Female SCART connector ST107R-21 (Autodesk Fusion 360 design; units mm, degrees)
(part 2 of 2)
sketch "Sketch19" plane through (0, 10, 0) normal (0, 1, 0) x axis (-1, 0, 0)
  line L1 (-41.65, 0) -> (-41.65, 5.21)
  line L2 (-39.24, 0) -> (-41.65, 0)
  line L3 (-39.24, 5.21) -> (-39.24, 0)
  line L4 (-39.74, 5.21) -> (-39.24, 5.21)
  line L5 (-39.74, 6.21) -> (-39.74, 5.21)
  line L6 (-37.34, 6.21) -> (-39.74, 6.21)
  line L7 (-37.34, 5.21) -> (-37.34, 6.21)
  line L8 (-37.84, 5.21) -> (-37.34, 5.21)
  line L9 (-37.84, 0) -> (-37.84, 5.21)
  line L10 (-35.43, 0) -> (-37.84, 0)
  line L11 (-35.43, 5.21) -> (-35.43, 0)
  line L12 (-35.93, 5.21) -> (-35.43, 5.21)
  line L13 (-35.93, 6.21) -> (-35.93, 5.21)
  line L14 (-33.53, 6.21) -> (-35.93, 6.21)
  line L15 (-33.53, 5.21) -> (-33.53, 6.21)
  line L16 (-34.03, 5.21) -> (-33.53, 5.21)
  line L17 (-34.03, 0) -> (-34.03, 5.21)
  line L18 (-31.62, 0) -> (-34.03, 0)
  line L19 (-31.62, 5.21) -> (-31.62, 0)
  line L20 (-32.12, 5.21) -> (-31.62, 5.21)
  line L21 (-32.12, 6.21) -> (-32.12, 5.21)
  line L22 (-29.72, 6.21) -> (-32.12, 6.21)
  line L23 (-29.72, 5.21) -> (-29.72, 6.21)
  line L24 (-30.22, 5.21) -> (-29.72, 5.21)
  line L25 (-30.22, 0) -> (-30.22, 5.21)
  line L26 (-27.81, 0) -> (-30.22, 0)
  line L27 (-27.81, 5.21) -> (-27.81, 0)
  line L28 (-28.31, 5.21) -> (-27.81, 5.21)
  line L29 (-28.31, 6.21) -> (-28.31, 5.21)
  line L30 (-25.91, 6.21) -> (-28.31, 6.21)
  line L31 (-25.91, 5.21) -> (-25.91, 6.21)
  line L32 (-26.41, 5.21) -> (-25.91, 5.21)
  line L33 (-26.41, 0) -> (-26.41, 5.21)
  line L34 (-24, 0) -> (-26.41, 0)
  line L35 (-24, 5.21) -> (-24, 0)
  line L36 (-24.5, 5.21) -> (-24, 5.21)
  line L37 (-24.5, 6.21) -> (-24.5, 5.21)
  line L38 (-22.1, 6.21) -> (-24.5, 6.21)
  line L39 (-22.1, 5.21) -> (-22.1, 6.21)
  line L40 (-22.6, 5.21) -> (-22.1, 5.21)
  line L41 (-22.6, 0) -> (-22.6, 5.21)
  line L42 (-20.19, 0) -> (-22.6, 0)
  line L43 (-20.19, 5.21) -> (-20.19, 0)
  line L44 (-20.69, 5.21) -> (-20.19, 5.21)
  line L45 (-20.69, 6.21) -> (-20.69, 5.21)
  line L46 (-18.29, 6.21) -> (-20.69, 6.21)
  line L47 (-18.29, 5.21) -> (-18.29, 6.21)
  line L48 (-18.79, 5.21) -> (-18.29, 5.21)
  line L49 (-18.79, 0) -> (-18.79, 5.21)
  line L50 (-16.38, 0) -> (-18.79, 0)
  line L51 (-16.38, 5.21) -> (-16.38, 0)
  line L52 (-16.88, 5.21) -> (-16.38, 5.21)
  line L53 (-16.88, 6.21) -> (-16.88, 5.21)
  line L54 (-14.48, 6.21) -> (-16.88, 6.21)
  line L55 (-14.48, 5.21) -> (-14.48, 6.21)
  line L56 (-14.98, 5.21) -> (-14.48, 5.21)
  line L57 (-14.98, 0) -> (-14.98, 5.21)
  line L58 (-12.57, 0) -> (-14.98, 0)
  line L59 (-12.57, 5.21) -> (-12.57, 0)
  line L60 (-13.07, 5.21) -> (-12.57, 5.21)
  line L61 (-13.07, 6.21) -> (-13.07, 5.21)
  line L62 (-10.67, 6.21) -> (-13.07, 6.21)
  line L63 (-10.67, 5.21) -> (-10.67, 6.21)
  line L64 (-11.17, 5.21) -> (-10.67, 5.21)
  line L65 (-11.17, 0) -> (-11.17, 5.21)
  line L66 (-8.76, 0) -> (-11.17, 0)
  line L67 (-8.76, 5.21) -> (-8.76, 0)
  line L68 (-9.26, 5.21) -> (-8.76, 5.21)
  line L69 (-9.26, 6.21) -> (-9.26, 5.21)
  line L70 (-6.86, 6.21) -> (-9.26, 6.21)
  line L71 (-6.86, 5.21) -> (-6.86, 6.21)
  line L72 (-7.36, 5.21) -> (-6.86, 5.21)
  line L73 (-7.36, 0) -> (-7.36, 5.21)
  line L74 (-5.0797, 0) -> (-7.36, 0)
  line L75 (-4.95, 5.21) -> (-4.95, 0.0028)
  line L76 (-5.45, 5.21) -> (-4.95, 5.21)
  line L77 (-5.45, 6.21) -> (-5.45, 5.21)
  line L78 (-3.05, 6.21) -> (-5.45, 6.21)
  line L79 (-3.05, 5.21) -> (-3.05, 6.21)
  line L80 (-3.55, 5.21) -> (-3.05, 5.21)
  line L81 (-3.55, 0.4193) -> (-3.55, 5.21)
  line L82 (-1.8712, 4.15) -> (-2.1135, 2.5506)
  line L83 (1.2056, 4.15) -> (-1.8712, 4.15)
  line L84 (1.2056, -1.7) -> (1.2056, 4.15)
  line L85 (0.2056, -1.7) -> (1.2056, -1.7)
  line L86 (2.7056, -6) -> (0.2056, -1.7)
  line L87 (2.7056, 4.15) -> (2.7056, -6)
  line L88 (3.2056, 4.15) -> (2.7056, 4.15)
  line L89 (3.2056, 12.35) -> (3.2056, 4.15)
  line L90 (-0.6288, 12.35) -> (3.2056, 12.35)
  line L91 (-0.5226, 13.0506) -> (-0.6288, 12.35)
  line L92 (-44.1, 16.5) -> (-3.4888, 16.5)
  line L93 (-47.1, 12.35) -> (-47.1, 13.5)
  line L94 (-50.7944, 12.35) -> (-47.1, 12.35)
  line L95 (-50.7944, 4.15) -> (-50.7944, 12.35)
  line L96 (-50.2944, 4.15) -> (-50.7944, 4.15)
  line L97 (-50.2944, -6) -> (-50.2944, 4.15)
  line L98 (-47.7944, -1.7) -> (-50.2944, -6)
  line L99 (-48.7944, -1.7) -> (-47.7944, -1.7)
  line L100 (-48.7944, 4.15) -> (-48.7944, -1.7)
  line L101 (-47.1, 4.15) -> (-48.7944, 4.15)
  line L102 (-47.1, 3) -> (-47.1, 4.15)
  line L103 (-43.05, 0) -> (-44.1, 0)
  line L104 (-43.05, 5.21) -> (-43.05, 0)
  line L105 (-43.55, 5.21) -> (-43.05, 5.21)
  line L106 (-43.55, 6.21) -> (-43.55, 5.21)
  line L107 (-41.15, 6.21) -> (-43.55, 6.21)
  line L108 (-41.15, 5.21) -> (-41.15, 6.21)
  line L109 (-41.65, 5.21) -> (-41.15, 5.21)
  line L110 (2.2056, 10.35) -> (-0.4884, 10.35)
  line L111 (2.2056, 6.15) -> (2.2056, 10.35)
  line L112 (-0.4884, 6.15) -> (2.2056, 6.15)
  line L113 (-0.4884, 10.35) -> (-0.4884, 6.15)
  line L114 (-49.7944, 6.15) -> (-47.1, 6.15)
  line L115 (-49.7944, 10.35) -> (-49.7944, 6.15)
  line L116 (-47.1, 10.35) -> (-49.7944, 10.35)
  line L117 (-47.1, 6.15) -> (-47.1, 10.35)
  line L118 (-26.405, 11.29) -> (-26.405, 10.29)
  line L119 (-24.005, 11.29) -> (-26.405, 11.29)
  line L120 (-24.005, 10.29) -> (-24.005, 11.29)
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  dimension "d126" distance = 0.1
  dimension "d127" distance = 0.1
  dimension "d128" distance = 0.3
  dimension "d129" distance = 0.3
extrude "Extrude15" new body sketch "Sketch19" along normal blind 5.1 and against normal blind 10 bodies "short_pin"
sketch "Sketch23" plane through (0, 0, 5.91) normal (0, 0, 1) x axis (-1, 0, 0)
  line L1 (-43.45, -15.1) -> (-43.45, 0)
  line L2 (-41.25, -15.1) -> (-43.45, -15.1)
  line L3 (-41.25, 0) -> (-41.25, -15.1)
  line L4 (-43.45, 0) -> (-41.25, 0)
  line L5 (-43.05, 0) -> (-41.65, 0)
  line L6 (-43.05, -7) -> (-43.05, 0)
  line L7 (-41.65, -7) -> (-43.05, -7)
  line L8 (-41.65, 0) -> (-41.65, -7)
  line L9 (-41.25, -8.6) -> (-43.45, -8.6)
  line L10 (-42.35, -15.1) -> (-42.35, -8.6)
  line L11 (-42.75, -15.1) -> (-42.75, -8.6)
  line L12 (-41.95, -15.1) -> (-41.95, -8.6)
  line L13 (-43.25, -15.1) -> (-43.25, 0)
  line L14 (-41.45, 0) -> (-41.45, -15.1)
  line L15 (-43.25, -9.9) -> (-42.75, -9.4)
  line L16 (-41.95, -9.4) -> (-42.75, -9.4)
  line L17 (-41.45, -9.9) -> (-41.95, -9.4)
  line L18 (-41.45, -14.2) -> (-41.95, -14.7)
  line L19 (-41.2429, -14.7) -> (-41.95, -14.7)
  line L20 (-43.25, -14.1825) -> (-42.75, -14.6825)
  point P6 (-41.65, 0)
  point P12 (-42.35, -8.6)
  point P13 (-42.35, -15.1)
  point P22 (-42.75, -9.4)
  point P23 (-43.25, -9.9)
  point P24 (-41.95, -9.4)
  point P25 (-41.45, -9.9)
  point P26 (-41.95, -14.7)
  point P27 (-41.45, -14.2)
  point P29 (-42.75, -14.6825)
  point P30 (-43.25, -14.1825)
  point P7 (-43.05, 0)
  point P8 (-43.05, -7)
  point P17 (-41.95, -15.1)
  horizontal L5
  vertical L6
  horizontal L7
  vertical L8
  coincident L4 P6
  midpoint L9 P12
  midpoint L2 P13
  perpendicular L2 L10
  parallel L2 L9
  horizontal L16
  coincident L11 P22
  coincident L13 P23
  coincident L12 P24
  coincident L14 P25
  horizontal L19
  coincident L12 P26
  coincident L14 P27
  coincident L11 P29
  coincident L13 P30
  perpendicular L18 L20
  dimension "d143" distance P7 P8 = 7
  dimension "d144" distance L1 L6 = 0.4
  dimension "d145" distance L3 L8 = 0.4
  dimension "d147" distance L2 L9 = 6.5
  dimension "d148" = 0.4
  dimension "d149" = -0.4
  dimension "d150" = -0.2
  dimension "d151" = -0.2
  dimension "d152" angle L15 L16 = 135
  dimension "d153" distance L9 L16 = 0.8
  dimension "d154" angle L18 L19 = 45
  dimension "d155" distance P17 P26 = 0.4
extrude "Extrude19" cut sketch "Sketch23" profile of L1 L2 L3 L4 L5 L6 L7 L8 L9 L11 L12 L13 L14 L15 L17 L18 L20 no distance stored
sketch "Sketch24" plane through (0, 15.1, 0) normal (0, 1, 0) x axis (-1, 0, 0)
  line L1 (-41.95, 5.91) -> (-41.95, 5.51)
  line L2 (-42.75, 5.91) -> (-41.95, 5.91)
  line L3 (-42.75, 5.51) -> (-42.75, 5.91)
  line L4 (-41.95, 5.51) -> (-42.75, 5.51)
  line L5 (-41.95, 5.91) -> (-42.75, 5.91)
  line L6 (-41.95, -4.5) -> (-41.95, 5.91)
  line L7 (-42.75, -4.5) -> (-41.95, -4.5)
  line L8 (-42.75, 5.91) -> (-42.75, -4.5)
  line L9 (-41.65, 0) -> (-43.05, 0)
  line L10 (-42.35, 5.91) -> (-42.35, -4.5)
  line L11 (-41.65, -4.5) -> (-41.65, 5.91)
  line L12 (-43.05, 5.91) -> (-43.05, -4.5)
  line L13 (-41.65, 4.51) -> (-41.95, 4.81)
  line L14 (-41.5257, 4.81) -> (-41.95, 4.81)
  line L15 (-43.05, 4.51) -> (-42.75, 4.81)
  line L16 (-41.95, 4.81) -> (-42.75, 4.81)
  line L17 (-41.65, 0.3) -> (-41.95, 0)
  line L18 (-41.5257, 0) -> (-41.95, 0)
  line L19 (-43.05, 0.3) -> (-42.75, 0)
  line L20 (-41.95, -4.1) -> (-42.35, -4.5)
  line L21 (-41.7843, -4.5) -> (-42.35, -4.5)
  line L22 (-42.75, -4.1) -> (-42.35, -4.5)
  point P4 (-42.75, 5.91)
  point P6 (-42.75, 5.91)
  point P12 (-42.35, -4.5)
  point P13 (-42.35, 5.91)
  point P18 (-41.95, 4.81)
  point P19 (-41.65, 4.51)
  point P21 (-42.75, 4.81)
  point P22 (-43.05, 4.51)
  point P23 (-41.95, 0)
  point P24 (-41.65, 0.3)
  point P26 (-42.75, 0)
  point P27 (-43.05, 0.3)
  point P28 (-41.95, -4.1)
  point P30 (-42.75, -4.1)
  point P3 (-41.95, 5.91)
  horizontal L5
  vertical L6
  horizontal L7
  vertical L8
  coincident P4 P6
  midpoint L7 P12
  midpoint L5 P13
  horizontal L14
  coincident L6 P18
  coincident L11 P19
  horizontal L16
  coincident L8 P21
  coincident L12 P22
  horizontal L18
  coincident L9 P23
  coincident L6 P23
  coincident L11 P24
  coincident L9 P26
  coincident L8 P26
  coincident L12 P27
  perpendicular L17 L19
  horizontal L21
  coincident L6 P28
  coincident L8 P30
  perpendicular L20 L22
  dimension "d159" distance L7 L9 = 4.5
  dimension "d160" = -0.3
  dimension "d161" = -0.3
  dimension "d162" angle L13 L14 = 45
  dimension "d163" angle L15 L16 = 135
  dimension "d164" distance P3 P18 = 1.1
  dimension "d165" angle L17 L18 = 45
  dimension "d166" angle L20 L21 = 45
extrude "Extrude20" add sketch "Sketch24" profile of L1 L2 L3 L4 L5 L6 L8 L9 L11 L12 L13 L15 L17 L19 L20 L22 along normal blind 0.4
fillet "Fillet10" radius 0.2
rectangular_pattern "R-Pattern2" countU 11 uSpaceDistance -3.81 vSpaceDistance 0 bodies "short_pin (1)", "short_pin (2)", "short_pin (3)", "short_pin (4)", "short_pin (5)", "short_pin (6)", "short_pin (7)", "short_pin (8)"
fillet "Fillet5" radius 0.2
fillet "Fillet11" radius 0.2
named bodies: "Case", "large_pin", "large_pin (1)", "large_pin (2)", "large_pin (3)", "large_pin (4)", "large_pin (5)", "large_pin (6)", "large_pin (7)", "large_pin (8)", "large_pin (9)", "short_pin", "short_pin (1)", "short_pin (2)", "short_pin (3)", "short_pin (4)", "short_pin (5)", "short_pin (6)", "short_pin (7)", "short_pin (8)", "short_pin (9)", "short_pin (10)"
